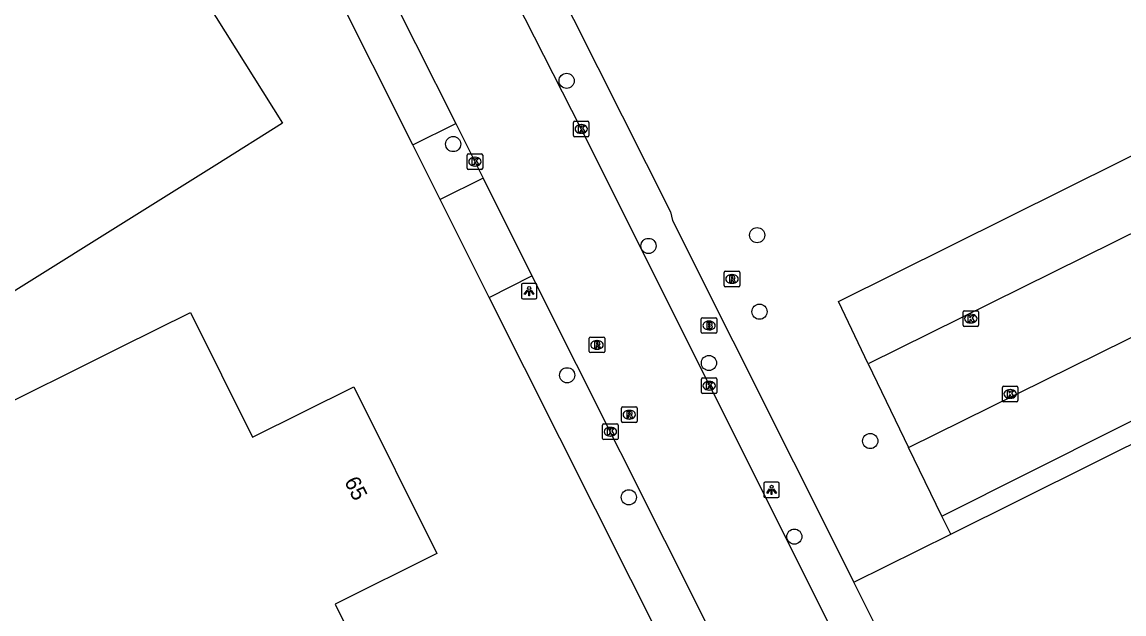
# Model space of a CAD drawing. Extents: x 158461 to 159795, y 387220 to 388672.
# Drawn here: x 158891.7 to 158962.8, y 387610.5 to 387648.6 of the extents above; entities that cross this region are included whole.
import ezdxf

# ---------------------------------------------------------------- set-up
doc = ezdxf.new("R2010")
doc.units = 0
for name, color, linetype in [('IMGEO_Boom', 7, 'Continuous'), ('IMGEO_Brandkraan', 7, 'Continuous'), ('IMGEO_Groenvoorziening', 7, 'Continuous'), ('IMGEO_Kolk', 7, 'Continuous'), ('IMGEO_Lichtpunt', 7, 'Continuous'), ('IMGEO_Pand', 7, 'Continuous'), ('IMGEO_Pand_nummerreeks', 7, 'Continuous'), ('IMGEO_Parkeervlak_open', 7, 'Continuous'), ('IMGEO_Rijbaan_lokaal_gesloten', 7, 'Continuous'), ('IMGEO_Rijbaan_lokaal_open', 7, 'Continuous'), ('IMGEO_Rioolput', 7, 'Continuous'), ('IMGEO_Voetpad_open', 7, 'Continuous')]:
    doc.layers.add(name, color=color, linetype=linetype)

msp = doc.modelspace()

# ---------------------------------------------------------------- linework, layer by layer
at = {"layer": 'IMGEO_Boom'}
for centre in [(158926.848, 387644.852), (158919.537, 387640.778), (158939.129, 387634.905), (158932.124, 387634.213), (158939.282, 387629.975), (158936.021, 387626.668), (158926.88, 387625.877), (158946.421, 387621.64), (158930.855, 387618.013), (158941.527, 387615.479)]:
    msp.add_circle(centre, 0.489, dxfattribs=at)
at = {"layer": 'IMGEO_Brandkraan'}
for p, q in [((158935.53, 387628.66), (158935.53, 387629.512)), ((158935.605, 387629.586), (158936.457, 387629.586)), ((158936.531, 387629.512), (158936.531, 387628.66)), ((158936.041, 387628.806), (158936.016, 387628.806)), ((158936.018, 387629.366), (158936.043, 387629.366)), ((158936.457, 387628.586), (158935.605, 387628.586))]:
    msp.add_line(p, q, dxfattribs=at)
for points in [[(158935.53, 387628.66), (158935.53, 387629.512)], [(158935.605, 387629.586), (158936.457, 387629.586)], [(158936.531, 387629.512), (158936.531, 387628.66)], [(158935.878, 387629.286), (158935.878, 387628.886), (158936.091, 387628.886)], [(158936.109, 387629.286), (158935.878, 387629.286)], [(158936.057, 387629.205), (158936.003, 387629.205), (158936.003, 387629.129)], [(158936.003, 387629.129), (158936.056, 387629.129)], [(158936.065, 387629.053), (158936.003, 387629.053), (158936.003, 387628.972)], [(158936.003, 387628.972), (158936.065, 387628.972)], [(158936.457, 387628.586), (158935.605, 387628.586)]]:
    msp.add_lwpolyline(points, dxfattribs=at)
for centre, radius, start, end in [((158935.607, 387629.51), 0.0765, 91.55205, 178.44795), ((158935.607, 387629.51), 0.0765, 91.55205, 178.44795), ((158936.455, 387629.51), 0.0765, 1.55205, 88.44795), ((158936.455, 387629.51), 0.0765, 1.55205, 88.44795), ((158936.058, 387629.167), 0.0379, 267.82845, 90.93552), ((158936.066, 387629.012), 0.0404, 269.87594, 90.50774), ((158936.097, 387629.137), 0.251, 268.66757, 293.53466), ((158936.113, 387629.141), 0.145, 59.4692, 91.53667), ((158936.138, 387629.188), 0.0922, 285.51372, 58.15012), ((158936.143, 387628.996), 0.105, 301.31148, 78.98903), ((158935.607, 387628.662), 0.0765, 181.55205, 268.44795), ((158935.607, 387628.662), 0.0765, 181.55205, 268.44795), ((158936.455, 387628.662), 0.0765, 271.55205, 358.44795), ((158936.455, 387628.662), 0.0765, 271.55205, 358.44795)]:
    msp.add_arc(centre, radius, start, end, dxfattribs=at)
for centre, major_axis, ratio, start_param, end_param in [((158936.017, 387629.086), (-0.387, 0.002), 0.722429, 4.712389, 7.853982), ((158936.042, 387629.086), (-0.39, 0.002), 0.717154, 1.570796, 4.712389)]:
    msp.add_ellipse(centre, major_axis=major_axis, ratio=ratio, start_param=start_param, end_param=end_param, dxfattribs=at)
at = {"layer": 'IMGEO_Groenvoorziening'}
msp.add_lwpolyline([(158945.355, 387612.535), (158951.609, 387615.644)], dxfattribs=at)
at = {"layer": 'IMGEO_Kolk'}
for p, q in [((158927.363, 387642.251), (158928.215, 387642.251)), ((158927.288, 387641.325), (158927.288, 387642.177)), ((158927.776, 387642.031), (158927.801, 387642.031)), ((158928.289, 387642.177), (158928.289, 387641.325)), ((158928.215, 387641.251), (158927.363, 387641.251)), ((158927.799, 387641.471), (158927.774, 387641.471)), ((158920.509, 387640.143), (158921.361, 387640.143)), ((158920.434, 387639.217), (158920.434, 387640.069)), ((158920.922, 387639.923), (158920.947, 387639.923)), ((158921.435, 387640.069), (158921.435, 387639.217)), ((158921.361, 387639.143), (158920.509, 387639.143)), ((158920.945, 387639.363), (158920.92, 387639.363)), ((158952.403, 387629.104), (158952.403, 387629.956)), ((158952.478, 387630.03), (158953.33, 387630.03)), ((158952.891, 387629.81), (158952.916, 387629.81)), ((158953.404, 387629.956), (158953.404, 387629.104)), ((158953.33, 387629.03), (158952.478, 387629.03)), ((158952.914, 387629.25), (158952.889, 387629.25)), ((158935.538, 387624.778), (158935.538, 387625.63)), ((158935.613, 387625.704), (158936.465, 387625.704)), ((158936.026, 387625.484), (158936.051, 387625.484)), ((158936.539, 387625.63), (158936.539, 387624.778)), ((158955.019, 387625.172), (158955.871, 387625.172)), ((158936.465, 387624.704), (158935.613, 387624.704)), ((158936.049, 387624.924), (158936.024, 387624.924)), ((158954.944, 387624.246), (158954.944, 387625.098)), ((158955.432, 387624.952), (158955.457, 387624.952)), ((158955.945, 387625.098), (158955.945, 387624.246)), ((158955.871, 387624.172), (158955.019, 387624.172)), ((158955.455, 387624.392), (158955.43, 387624.392)), ((158929.167, 387621.813), (158929.167, 387622.665)), ((158929.242, 387622.739), (158930.094, 387622.739)), ((158929.655, 387622.519), (158929.68, 387622.519)), ((158930.168, 387622.665), (158930.168, 387621.813)), ((158930.094, 387621.739), (158929.242, 387621.739)), ((158929.678, 387621.959), (158929.653, 387621.959))]:
    msp.add_line(p, q, dxfattribs=at)
for points in [[(158927.363, 387642.251), (158928.215, 387642.251)], [(158927.288, 387641.325), (158927.288, 387642.177)], [(158927.609, 387641.951), (158927.732, 387641.951), (158927.732, 387641.8), (158927.862, 387641.951), (158928.026, 387641.951), (158927.88, 387641.8), (158928.033, 387641.551), (158927.881, 387641.551), (158927.796, 387641.715), (158927.732, 387641.648), (158927.732, 387641.551), (158927.609, 387641.551), (158927.609, 387641.951)], [(158928.289, 387642.177), (158928.289, 387641.325)], [(158928.215, 387641.251), (158927.363, 387641.251)], [(158920.509, 387640.143), (158921.361, 387640.143)], [(158920.434, 387639.217), (158920.434, 387640.069)], [(158920.755, 387639.843), (158920.878, 387639.843), (158920.878, 387639.692), (158921.008, 387639.843), (158921.172, 387639.843), (158921.026, 387639.692), (158921.179, 387639.443), (158921.027, 387639.443), (158920.942, 387639.607), (158920.878, 387639.54), (158920.878, 387639.443), (158920.755, 387639.443), (158920.755, 387639.843)], [(158921.435, 387640.069), (158921.435, 387639.217)], [(158921.361, 387639.143), (158920.509, 387639.143)], [(158952.403, 387629.104), (158952.403, 387629.956)], [(158952.478, 387630.03), (158953.33, 387630.03)], [(158952.724, 387629.73), (158952.847, 387629.73), (158952.847, 387629.579), (158952.977, 387629.73), (158953.141, 387629.73), (158952.995, 387629.579), (158953.148, 387629.33), (158952.996, 387629.33), (158952.911, 387629.494), (158952.847, 387629.427), (158952.847, 387629.33), (158952.724, 387629.33), (158952.724, 387629.73)], [(158953.404, 387629.956), (158953.404, 387629.104)], [(158953.33, 387629.03), (158952.478, 387629.03)], [(158935.538, 387624.778), (158935.538, 387625.63)], [(158935.613, 387625.704), (158936.465, 387625.704)], [(158935.859, 387625.404), (158935.982, 387625.404), (158935.982, 387625.253), (158936.112, 387625.404), (158936.276, 387625.404), (158936.13, 387625.253), (158936.283, 387625.004), (158936.131, 387625.004), (158936.046, 387625.168), (158935.982, 387625.101), (158935.982, 387625.004), (158935.859, 387625.004), (158935.859, 387625.404)], [(158936.539, 387625.63), (158936.539, 387624.778)], [(158955.019, 387625.172), (158955.871, 387625.172)], [(158936.465, 387624.704), (158935.613, 387624.704)], [(158954.944, 387624.246), (158954.944, 387625.098)], [(158955.265, 387624.872), (158955.388, 387624.872), (158955.388, 387624.721), (158955.518, 387624.872), (158955.682, 387624.872), (158955.536, 387624.721), (158955.689, 387624.472), (158955.537, 387624.472), (158955.452, 387624.636), (158955.388, 387624.569), (158955.388, 387624.472), (158955.265, 387624.472), (158955.265, 387624.872)], [(158955.945, 387625.098), (158955.945, 387624.246)], [(158955.871, 387624.172), (158955.019, 387624.172)], [(158929.167, 387621.813), (158929.167, 387622.665)], [(158929.242, 387622.739), (158930.094, 387622.739)], [(158929.488, 387622.439), (158929.611, 387622.439), (158929.611, 387622.288), (158929.741, 387622.439), (158929.905, 387622.439), (158929.759, 387622.288), (158929.912, 387622.039), (158929.76, 387622.039), (158929.675, 387622.203), (158929.611, 387622.136), (158929.611, 387622.039), (158929.488, 387622.039), (158929.488, 387622.439)], [(158930.168, 387622.665), (158930.168, 387621.813)], [(158930.094, 387621.739), (158929.242, 387621.739)]]:
    msp.add_lwpolyline(points, dxfattribs=at)
for centre, start, end in [((158927.365, 387642.175), 91.55205, 178.44795), ((158927.365, 387642.175), 91.55205, 178.44795), ((158928.213, 387642.175), 1.55205, 88.44795), ((158928.213, 387642.175), 1.55205, 88.44795), ((158927.365, 387641.327), 181.55205, 268.44795), ((158927.365, 387641.327), 181.55205, 268.44795), ((158928.213, 387641.327), 271.55205, 358.44795), ((158928.213, 387641.327), 271.55205, 358.44795), ((158920.511, 387640.067), 91.55205, 178.44795), ((158920.511, 387640.067), 91.55205, 178.44795), ((158921.359, 387640.067), 1.55205, 88.44795), ((158921.359, 387640.067), 1.55205, 88.44795), ((158920.511, 387639.219), 181.55205, 268.44795), ((158920.511, 387639.219), 181.55205, 268.44795), ((158921.359, 387639.219), 271.55205, 358.44795), ((158921.359, 387639.219), 271.55205, 358.44795), ((158952.48, 387629.954), 91.55205, 178.44795), ((158952.48, 387629.954), 91.55205, 178.44795), ((158953.328, 387629.954), 1.55205, 88.44795), ((158953.328, 387629.954), 1.55205, 88.44795), ((158952.48, 387629.106), 181.55205, 268.44795), ((158952.48, 387629.106), 181.55205, 268.44795), ((158953.328, 387629.106), 271.55205, 358.44795), ((158953.328, 387629.106), 271.55205, 358.44795), ((158935.615, 387625.628), 91.55205, 178.44795), ((158935.615, 387625.628), 91.55205, 178.44795), ((158936.463, 387625.628), 1.55205, 88.44795), ((158936.463, 387625.628), 1.55205, 88.44795), ((158955.021, 387625.096), 91.55205, 178.44795), ((158955.021, 387625.096), 91.55205, 178.44795), ((158955.869, 387625.096), 1.55205, 88.44795), ((158955.869, 387625.096), 1.55205, 88.44795), ((158935.615, 387624.78), 181.55205, 268.44795), ((158935.615, 387624.78), 181.55205, 268.44795), ((158936.463, 387624.78), 271.55205, 358.44795), ((158936.463, 387624.78), 271.55205, 358.44795), ((158955.021, 387624.248), 181.55205, 268.44795), ((158955.021, 387624.248), 181.55205, 268.44795), ((158955.869, 387624.248), 271.55205, 358.44795), ((158955.869, 387624.248), 271.55205, 358.44795), ((158929.244, 387622.663), 91.55205, 178.44795), ((158929.244, 387622.663), 91.55205, 178.44795), ((158930.092, 387622.663), 1.55205, 88.44795), ((158930.092, 387622.663), 1.55205, 88.44795), ((158929.244, 387621.815), 181.55205, 268.44795), ((158929.244, 387621.815), 181.55205, 268.44795), ((158930.092, 387621.815), 271.55205, 358.44795), ((158930.092, 387621.815), 271.55205, 358.44795)]:
    msp.add_arc(centre, 0.0765, start, end, dxfattribs=at)
for centre, major_axis, ratio, start_param, end_param in [((158927.775, 387641.751), (-0.387, 0.002), 0.722429, 4.712389, 7.853982), ((158927.8, 387641.751), (-0.39, 0.002), 0.717154, 1.570796, 4.712389), ((158920.921, 387639.643), (-0.387, 0.002), 0.722429, 4.712389, 7.853982), ((158920.946, 387639.643), (-0.39, 0.002), 0.717154, 1.570796, 4.712389), ((158952.89, 387629.53), (-0.387, 0.002), 0.722429, 4.712389, 7.853982), ((158952.915, 387629.53), (-0.39, 0.002), 0.717154, 1.570796, 4.712389), ((158936.025, 387625.204), (-0.387, 0.002), 0.722429, 4.712389, 7.853982), ((158936.05, 387625.204), (-0.39, 0.002), 0.717154, 1.570796, 4.712389), ((158955.431, 387624.672), (-0.387, 0.002), 0.722429, 4.712389, 7.853982), ((158955.456, 387624.672), (-0.39, 0.002), 0.717154, 1.570796, 4.712389), ((158929.654, 387622.239), (-0.387, 0.002), 0.722429, 4.712389, 7.853982), ((158929.679, 387622.239), (-0.39, 0.002), 0.717154, 1.570796, 4.712389)]:
    msp.add_ellipse(centre, major_axis=major_axis, ratio=ratio, start_param=start_param, end_param=end_param, dxfattribs=at)
at = {"layer": 'IMGEO_Lichtpunt'}
for p, q in [((158923.933, 387631.703), (158923.933, 387630.896)), ((158923.933, 387631.703), (158923.933, 387630.896)), ((158924.835, 387631.798), (158924.027, 387631.798)), ((158924.835, 387631.798), (158924.027, 387631.798)), ((158924.929, 387630.896), (158924.929, 387631.703)), ((158924.929, 387630.896), (158924.929, 387631.703)), ((158924.027, 387630.802), (158924.835, 387630.802)), ((158924.027, 387630.802), (158924.835, 387630.802)), ((158939.563, 387618.893), (158939.563, 387618.086)), ((158939.563, 387618.893), (158939.563, 387618.086)), ((158940.465, 387618.988), (158939.657, 387618.988)), ((158940.465, 387618.988), (158939.657, 387618.988)), ((158940.559, 387618.086), (158940.559, 387618.893)), ((158940.559, 387618.086), (158940.559, 387618.893)), ((158939.657, 387617.992), (158940.465, 387617.992)), ((158939.657, 387617.992), (158940.465, 387617.992))]:
    msp.add_line(p, q, dxfattribs=at)
for points in [[(158924.307, 387631.367), (158924.346, 387631.339), (158924.158, 387631.077), (158924.12, 387631.104), (158924.307, 387631.367)], [(158924.409, 387631.319), (158924.456, 387631.319), (158924.456, 387630.997), (158924.409, 387630.997), (158924.409, 387631.319)], [(158924.519, 387631.339), (158924.557, 387631.366), (158924.744, 387631.104), (158924.705, 387631.076), (158924.519, 387631.339)], [(158939.937, 387618.557), (158939.976, 387618.529), (158939.788, 387618.267), (158939.75, 387618.294), (158939.937, 387618.557)], [(158940.039, 387618.509), (158940.086, 387618.509), (158940.086, 387618.187), (158940.039, 387618.187), (158940.039, 387618.509)], [(158940.149, 387618.529), (158940.187, 387618.556), (158940.374, 387618.294), (158940.335, 387618.266), (158940.149, 387618.529)]]:
    msp.add_lwpolyline(points, dxfattribs=at)
for centre in [(158924.432, 387631.501), (158940.062, 387618.691)]:
    msp.add_circle(centre, 0.0994, dxfattribs=at)
for centre, start, end in [((158924.027, 387631.703), 90, 180), ((158924.027, 387631.703), 90, 180), ((158924.835, 387631.703), 0, 90), ((158924.835, 387631.703), 0, 90), ((158924.027, 387630.896), 180, 270), ((158924.027, 387630.896), 180, 270), ((158924.835, 387630.896), 270, 0), ((158924.835, 387630.896), 270, 360), ((158939.657, 387618.893), 90, 180), ((158939.657, 387618.893), 90, 180), ((158940.465, 387618.893), 0, 90), ((158940.465, 387618.893), 0, 90), ((158939.657, 387618.086), 180, 270), ((158939.657, 387618.086), 180, 270), ((158940.465, 387618.086), 270, 0), ((158940.465, 387618.086), 270, 360)]:
    msp.add_arc(centre, 0.0946, start, end, dxfattribs=at)
at = {"layer": 'IMGEO_Pand'}
for points in [[(158883.635, 387620.442), (158869.854, 387642.432), (158867.642, 387645.962), (158864.987, 387650.199), (158869.238, 387652.895), (158867.621, 387655.417), (158878.047, 387661.941), (158877.239, 387663.227), (158877.512, 387663.377), (158878.323, 387662.112), (158883.343, 387665.253), (158888.459, 387668.453), (158894.225, 387667.08), (158896.065, 387664.099), (158895.119, 387663.494), (158908.535, 387642.117), (158904.295, 387639.469), (158885.82, 387627.929), (158888.801, 387623.081)], [(158888.801, 387623.081), (158898.121, 387627.704), (158902.597, 387629.931), (158906.604, 387621.885), (158913.12, 387625.134), (158918.477, 387614.393), (158911.935, 387611.134), (158915.862, 387603.234), (158911.387, 387601.004), (158897.995, 387594.33), (158886.575, 387615.835), (158883.635, 387620.442)]]:
    msp.add_lwpolyline(points, dxfattribs=at)
at = {"layer": 'IMGEO_Parkeervlak_open'}
for points in [[(158946.279, 387626.609), (158944.377, 387630.625), (159006.332, 387661.445), (159008.345, 387657.448)], [(158951.046, 387616.798), (158948.883, 387621.227)]]:
    msp.add_lwpolyline(points, dxfattribs=at)
at = {"layer": 'IMGEO_Rijbaan_lokaal_gesloten'}
for points in [[(158944.884, 387607.596), (158927.789, 387641.751), (158919.992, 387657.088), (158917.009, 387662.578), (158914.339, 387667.291), (158911.457, 387672.114), (158905.886, 387680.514)], [(158914.511, 387652.445), (158919.71, 387642.093)], [(158919.71, 387642.093), (158921.465, 387638.578)], [(158921.465, 387638.578), (158924.613, 387632.28)], [(158924.613, 387632.28), (158936.019, 387609.551)]]:
    msp.add_lwpolyline(points, dxfattribs=at)
at = {"layer": 'IMGEO_Rijbaan_lokaal_open'}
for points in [[(159008.345, 387657.448), (158986.006, 387646.24), (158946.279, 387626.609)], [(158948.883, 387621.227), (158991.129, 387642.076), (159011.079, 387651.953)], [(158946.279, 387626.609), (158948.883, 387621.227)]]:
    msp.add_lwpolyline(points, dxfattribs=at)
at = {"layer": 'IMGEO_Rioolput'}
for p, q in [((158937.008, 387631.657), (158937.008, 387632.509)), ((158937.083, 387632.583), (158937.935, 387632.583)), ((158937.496, 387632.363), (158937.521, 387632.363)), ((158938.009, 387632.509), (158938.009, 387631.657)), ((158937.935, 387631.583), (158937.083, 387631.583)), ((158937.519, 387631.803), (158937.494, 387631.803)), ((158928.305, 387627.411), (158928.305, 387628.263)), ((158928.38, 387628.337), (158929.232, 387628.337)), ((158928.793, 387628.117), (158928.818, 387628.117)), ((158929.306, 387628.263), (158929.306, 387627.411)), ((158929.232, 387627.337), (158928.38, 387627.337)), ((158928.816, 387627.557), (158928.791, 387627.557)), ((158930.384, 387622.911), (158930.384, 387623.763)), ((158930.459, 387623.837), (158931.311, 387623.837)), ((158931.385, 387623.763), (158931.385, 387622.911)), ((158930.895, 387623.057), (158930.87, 387623.057)), ((158930.872, 387623.617), (158930.897, 387623.617)), ((158931.311, 387622.837), (158930.459, 387622.837))]:
    msp.add_line(p, q, dxfattribs=at)
for points in [[(158937.008, 387631.657), (158937.008, 387632.509)], [(158937.083, 387632.583), (158937.935, 387632.583)], [(158937.597, 387632.281), (158937.345, 387632.283), (158937.345, 387631.883)], [(158938.009, 387632.509), (158938.009, 387631.657)], [(158937.935, 387631.583), (158937.083, 387631.583)], [(158937.345, 387631.883), (158937.469, 387631.883), (158937.469, 387632.045), (158937.48, 387632.045)], [(158937.523, 387632.202), (158937.469, 387632.202), (158937.469, 387632.121)], [(158937.469, 387632.121), (158937.521, 387632.121)], [(158937.527, 387632.016), (158937.598, 387631.883), (158937.738, 387631.883), (158937.673, 387632.009)], [(158928.305, 387627.411), (158928.305, 387628.263)], [(158928.38, 387628.337), (158929.232, 387628.337)], [(158928.894, 387628.035), (158928.642, 387628.037), (158928.642, 387627.637)], [(158929.306, 387628.263), (158929.306, 387627.411)], [(158929.232, 387627.337), (158928.38, 387627.337)], [(158928.642, 387627.637), (158928.766, 387627.637), (158928.766, 387627.799), (158928.777, 387627.799)], [(158928.82, 387627.956), (158928.766, 387627.956), (158928.766, 387627.875)], [(158928.766, 387627.875), (158928.818, 387627.875)], [(158928.824, 387627.77), (158928.895, 387627.637), (158929.035, 387627.637), (158928.97, 387627.763)], [(158930.384, 387622.911), (158930.384, 387623.763)], [(158930.459, 387623.837), (158931.311, 387623.837)], [(158931.385, 387623.763), (158931.385, 387622.911)], [(158930.973, 387623.535), (158930.721, 387623.537), (158930.721, 387623.137)], [(158930.721, 387623.137), (158930.845, 387623.137), (158930.845, 387623.299), (158930.856, 387623.299)], [(158930.899, 387623.456), (158930.845, 387623.456), (158930.845, 387623.375)], [(158930.845, 387623.375), (158930.897, 387623.375)], [(158930.903, 387623.27), (158930.974, 387623.137), (158931.114, 387623.137), (158931.049, 387623.263)], [(158931.311, 387622.837), (158930.459, 387622.837)]]:
    msp.add_lwpolyline(points, dxfattribs=at)
for centre, radius, start, end in [((158937.085, 387632.507), 0.0765, 91.55205, 178.44795), ((158937.085, 387632.507), 0.0765, 91.55205, 178.44795), ((158937.596, 387632.171), 0.109, 350.36119, 89.41601), ((158937.933, 387632.507), 0.0765, 1.55205, 88.44795), ((158937.933, 387632.507), 0.0765, 1.55205, 88.44795), ((158937.085, 387631.659), 0.0765, 181.55205, 268.44795), ((158937.085, 387631.659), 0.0765, 181.55205, 268.44795), ((158937.479, 387631.992), 0.0533, 26.02933, 88.69889), ((158937.505, 387632.31), 0.19, 274.7715, 282.96867), ((158937.529, 387632.106), 0.0964, 77.00612, 93.18647), ((158937.543, 387632.163), 0.0378, 276.66336, 79.67722), ((158937.594, 387632.171), 0.112, 277.58423, 350.98172), ((158937.578, 387631.956), 0.108, 29.51342, 73.79051), ((158937.933, 387631.659), 0.0765, 271.55205, 358.44795), ((158937.933, 387631.659), 0.0765, 271.55205, 358.44795), ((158928.382, 387628.261), 0.0765, 91.55205, 178.44795), ((158928.382, 387628.261), 0.0765, 91.55205, 178.44795), ((158928.893, 387627.925), 0.109, 350.36119, 89.41601), ((158929.23, 387628.261), 0.0765, 1.55205, 88.44795), ((158929.23, 387628.261), 0.0765, 1.55205, 88.44795), ((158928.382, 387627.413), 0.0765, 181.55205, 268.44795), ((158928.382, 387627.413), 0.0765, 181.55205, 268.44795), ((158928.776, 387627.746), 0.0533, 26.02933, 88.69889), ((158928.802, 387628.064), 0.19, 274.7715, 282.96867), ((158928.826, 387627.86), 0.0964, 77.00612, 93.18647), ((158928.84, 387627.917), 0.0378, 276.66336, 79.67722), ((158928.891, 387627.925), 0.112, 277.58423, 350.98172), ((158928.875, 387627.71), 0.108, 29.51342, 73.79051), ((158929.23, 387627.413), 0.0765, 271.55205, 358.44795), ((158929.23, 387627.413), 0.0765, 271.55205, 358.44795), ((158930.461, 387623.761), 0.0765, 91.55205, 178.44795), ((158930.461, 387623.761), 0.0765, 91.55205, 178.44795), ((158931.309, 387623.761), 0.0765, 1.55205, 88.44795), ((158931.309, 387623.761), 0.0765, 1.55205, 88.44795), ((158930.855, 387623.246), 0.0533, 26.02933, 88.69889), ((158930.881, 387623.564), 0.19, 274.7715, 282.96867), ((158930.905, 387623.36), 0.0964, 77.00612, 93.18647), ((158930.919, 387623.417), 0.0378, 276.66336, 79.67722), ((158930.972, 387623.425), 0.109, 350.36119, 89.41601), ((158930.97, 387623.425), 0.112, 277.58423, 350.98172), ((158930.954, 387623.21), 0.108, 29.51342, 73.79051), ((158930.461, 387622.913), 0.0765, 181.55205, 268.44795), ((158930.461, 387622.913), 0.0765, 181.55205, 268.44795), ((158931.309, 387622.913), 0.0765, 271.55205, 358.44795), ((158931.309, 387622.913), 0.0765, 271.55205, 358.44795)]:
    msp.add_arc(centre, radius, start, end, dxfattribs=at)
for centre, major_axis, ratio, start_param, end_param in [((158937.495, 387632.083), (-0.387, 0.002), 0.722429, 4.712389, 7.853982), ((158937.52, 387632.083), (-0.39, 0.002), 0.717154, 1.570796, 4.712389), ((158928.792, 387627.837), (-0.387, 0.002), 0.722429, 4.712389, 7.853982), ((158928.817, 387627.837), (-0.39, 0.002), 0.717154, 1.570796, 4.712389), ((158930.871, 387623.337), (-0.387, 0.002), 0.722429, 4.712389, 7.853982), ((158930.896, 387623.337), (-0.39, 0.002), 0.717154, 1.570796, 4.712389)]:
    msp.add_ellipse(centre, major_axis=major_axis, ratio=ratio, start_param=start_param, end_param=end_param, dxfattribs=at)
at = {"layer": 'IMGEO_Voetpad_open'}
for points in [[(158908.159, 387682.093), (158913.743, 387673.679), (158916.645, 387668.895), (158919.566, 387663.783), (158922.608, 387658.152), (158933.55, 387636.401), (158933.668, 387635.841), (158945.355, 387612.535)], [(158951.046, 387616.798), (158968.024, 387625.33), (159013.219, 387647.788), (159011.079, 387651.953)], [(158916.94, 387640.737), (158911.753, 387651.052)], [(158916.94, 387640.737), (158919.71, 387642.093)], [(158918.695, 387637.196), (158916.94, 387640.737)], [(158921.465, 387638.578), (158918.695, 387637.196)], [(158921.856, 387630.891), (158918.695, 387637.196)], [(158921.856, 387630.891), (158924.613, 387632.28)], [(158933.26, 387608.176), (158921.856, 387630.891)], [(158951.609, 387615.644), (158969.841, 387624.709)], [(158951.609, 387615.644), (158951.046, 387616.798)], [(158949.423, 387571.741), (158957.461, 387576.099), (158957.303, 387576.367), (158962.13, 387578.938), (158947.594, 387608.591), (158947.378, 387608.501), (158945.355, 387612.535)]]:
    msp.add_lwpolyline(points, dxfattribs=at)

# ---------------------------------------------------------------- texts
at = {"layer": 'IMGEO_Pand_nummerreeks'}
msp.add_text('65', height=1, rotation=296.50741, dxfattribs=at).set_placement((158912.494, 387619.039))

doc.saveas('drawing.dxf')
